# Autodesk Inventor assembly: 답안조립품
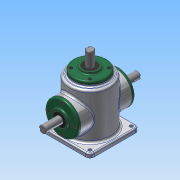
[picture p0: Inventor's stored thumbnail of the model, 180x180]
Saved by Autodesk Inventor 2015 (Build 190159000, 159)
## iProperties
Created: 2015-10
Part Number: 답안조립품
Document SubType Name: Assembly
Designer: 602-22
Author: 602-22
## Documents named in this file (14)
- C:\Users\602-22\Desktop\451008V1010\답안조립품.iam
- C:\Users\602-22\Desktop\451008V1010\본체.ipt
- C:\Users\602-22\Desktop\451008V1010\메인 축.ipt
- 메인 축.ipt
- C:\Users\602-22\Desktop\451008V1010\키 5x5.ipt
- C:\Users\602-22\Desktop\451008V1010\베어링 6203.ipt
- C:\Users\602-22\Desktop\451008V1010\커버.ipt
- C:\Users\602-22\Desktop\451008V1010\메인 베벨기어.ipt
- C:\Users\602-22\Desktop\451008V1010\M4.ipt
- C:\Users\602-22\Desktop\451008V1010\서브 축.ipt
- 서브 축.ipt
- C:\Users\602-22\Desktop\451008V1010\키 4x4.ipt
- C:\Users\602-22\Desktop\451008V1010\서브 베벨기어.ipt
- C:\Users\602-22\Desktop\451008V1010\오일실.ipt
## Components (12 placed, 1 different names)
1. M4:1 — Insert:11
2. M4:3
3. M4:4
4. M4:5
5. M4:2 — Insert:12
6. M4:6
7. M4:7
8. M4:8
9. M4:9 — Insert:18
10. M4:10
11. M4:11
12. M4:12
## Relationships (3: Insert 3)
- Insert:11: M4:1
- Insert:12: M4:2
- Insert:18: M4:9
